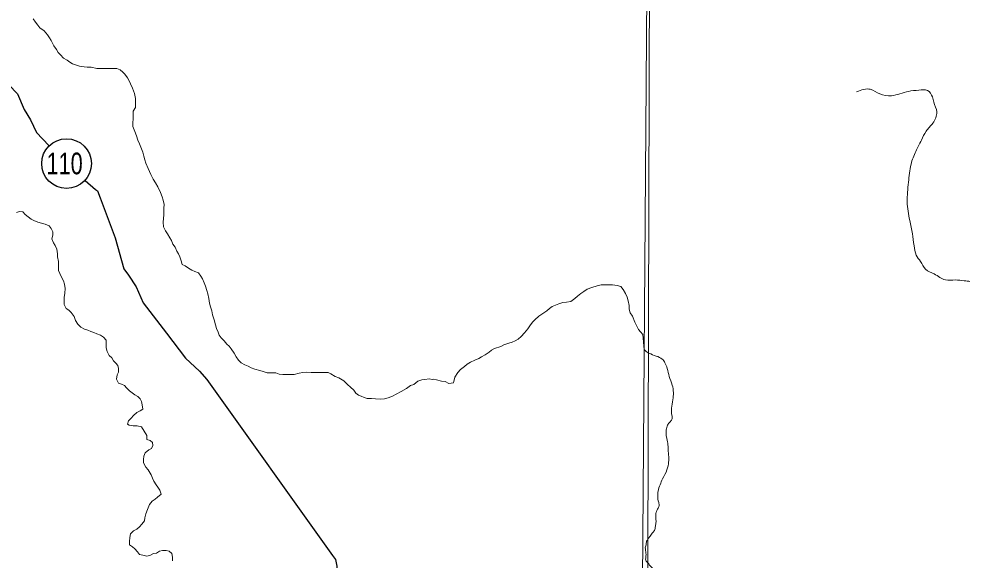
# Model space of a CAD drawing. Extents: x -1643653 to 4543381, y 1624270 to 13878484.
# Drawn here: x 616478 to 619526, y 8901080 to 8902830 of the extents above; entities that cross this region are included whole.
import ezdxf
from ezdxf.enums import TextEntityAlignment as Align

# ---------------------------------------------------------------- set-up
doc = ezdxf.new("R2010")
doc.units = 0
doc.header["$LTSCALE"] = 200
doc.layers.add('1', color=7, linetype='Continuous', lineweight=13)
doc.layers.add('6', color=7, linetype='Continuous', lineweight=13)

msp = doc.modelspace()

# ---------------------------------------------------------------- linework, layer by layer
at = {"layer": '1', "lineweight": 25}
msp.add_spline([(814781, 9009175.5), (814787.2, 9009173.4), (814796.9, 9009173.4), (814799.4, 9009172.4), (814805.1, 9009174.5), (814805.6, 9009176.5), (814811.7, 9009179.5), (814811.7, 9009179.5), (814801.5, 9009181), (814790.7, 9009181.5), (814784.1, 9009183.1), (814777.4, 9009185.1), (814778.4, 9009175.5)], degree=3, dxfattribs=at)
at = {"layer": '6'}
for points in [[(618663, 8924716.1), (618558.3, 8909803.7), (618456.5, 8896026.7)], [(616524, 8902830.2), (616532, 8902818.9), (616539.1, 8902809.7), (616546.1, 8902800.5), (616560.3, 8902791.2), (616570.4, 8902777.9), (616577.4, 8902768.7), (616582.5, 8902759.5), (616591.5, 8902743.1), (616599.6, 8902730.8), (616605.6, 8902721.6), (616612.7, 8902713.4), (616622.8, 8902703.2), (616633.9, 8902696), (616643, 8902689.8), (616651.3, 8902684.9), (616664.3, 8902680.5), (616674.5, 8902677.4), (616688.7, 8902675.3), (616698.9, 8902674.2), (616712.1, 8902674.1), (616730.4, 8902669.9), (616742.6, 8902669.8), (616754.8, 8902669.7), (616772.1, 8902669.6), (616784.3, 8902669.6), (616794.5, 8902669.5), (616805.6, 8902665.3), (616813.7, 8902658.2), (616820.8, 8902651), (616828.8, 8902639.7), (616834.9, 8902629.5), (616838.9, 8902620.3), (616844.9, 8902606), (616851.9, 8902588.6), (616854.8, 8902572.3), (616854.7, 8902555), (616854.6, 8902543.8), (616847.4, 8902531.6), (616847.3, 8902519.4), (616847.2, 8902508.2), (616846.1, 8902492.9), (616846.1, 8902481.7), (616853.1, 8902466.4), (616858.1, 8902452.1), (616863, 8902437.8), (616868, 8902425.5), (616872, 8902415.3), (616879.1, 8902399), (616882, 8902385.7), (616885, 8902374.5), (616888, 8902363.3), (616896, 8902345.9)], [(616896, 8902345.9), (616900, 8902336.7), (616905, 8902326.5), (616912, 8902312.2), (616920.1, 8902299.9), (616927.1, 8902286.6), (616936.1, 8902269.2), (616941.1, 8902254.9), (616944.1, 8902243.7), (616947.1, 8902230.4), (616947, 8902218.2), (616946.9, 8902207), (616946.8, 8902196.8), (616945.7, 8902184.6), (616944.6, 8902172.4), (616945.6, 8902158.1), (616951.6, 8902144.8), (616958.6, 8902134.6), (616965.7, 8902122.3), (616971.7, 8902114.1), (616975.7, 8902101.9), (616982.7, 8902091.7), (616988.8, 8902079.4), (616993.8, 8902070.2), (616997.8, 8902061), (617002.8, 8902047.7), (617005.7, 8902035.5), (617015.9, 8902031.3), (617026, 8902024.1), (617037.2, 8902018), (617046.3, 8902013.8), (617058.5, 8902008.7), (617066.5, 8901998.4), (617071.5, 8901989.2), (617076.5, 8901976.9), (617081.6, 8901965.7), (617085.5, 8901952.4)], [(616470.2, 8902203.8), (616480.3, 8902206.8), (616490.5, 8902205.7), (616498.6, 8902197.5), (616507.7, 8902190.3), (616517.8, 8902182.1), (616526.9, 8902178), (616539.1, 8902172.8), (616551.3, 8902169.7), (616563.5, 8902166.5), (616575.7, 8902161.3), (616582.7, 8902152.1), (616587.7, 8902141.9), (616587.7, 8902130.7), (616584.5, 8902118.5), (616590.5, 8902106.2), (616595.6, 8902097)], [(616595.6, 8902097), (616600.6, 8902085.8), (616602.5, 8902070.5), (616603.4, 8902060.3), (616606.4, 8902046), (616606.3, 8902035.8), (616606.2, 8902016.5), (616610.2, 8902007.3), (616616.2, 8901995), (616622.2, 8901982.8), (616625.2, 8901972.6), (616627.2, 8901958.3), (616627.1, 8901943), (616624.9, 8901928.8), (616624.8, 8901917.6), (616624.8, 8901906.3), (616630.8, 8901894.1), (616639.9, 8901888.9), (616647, 8901880.7), (616657.1, 8901868.4), (616661, 8901855.2), (616669.1, 8901842.9), (616678.2, 8901833.7)], [(617085.5, 8901952.4), (617088.5, 8901941.2), (617092.5, 8901925.9), (617094.4, 8901910.6), (617097.4, 8901899.4), (617101.3, 8901886.1), (617104.3, 8901872.9), (617109.3, 8901857.6), (617113.2, 8901841.2), (617117.2, 8901829), (617122.2, 8901817.7), (617125.2, 8901807.5), (617132.3, 8901799.3), (617141.4, 8901789.1), (617150.5, 8901778.8), (617157.5, 8901771.7), (617164.6, 8901763.5), (617173.7, 8901749.1), (617180.7, 8901737.9), (617187.7, 8901726.6), (617196.8, 8901718.4), (617208, 8901712.2), (617219.1, 8901707.1), (617229.3, 8901701.9), (617240.4, 8901697.8), (617256.7, 8901693.6), (617267.8, 8901690.5), (617281, 8901686.3), (617293.2, 8901686.2), (617308.5, 8901686.1), (617319.7, 8901682), (617330.8, 8901680.9), (617345.1, 8901680.8), (617355.3, 8901680.7), (617367.5, 8901680.7), (617383.8, 8901684.6), (617396, 8901686.6), (617407.2, 8901687.5), (617422.5, 8901687.4), (617437.7, 8901687.3), (617454, 8901687.2), (617464.2, 8901687.2), (617477.4, 8901687.1), (617486.5, 8901682.9), (617500.7, 8901673.7), (617511.8, 8901669.6), (617528.1, 8901660.3), (617540.2, 8901648), (617550.3, 8901639.8), (617560.4, 8901629.5), (617567.5, 8901620.3), (617575.6, 8901614.1), (617584.7, 8901610), (617593.8, 8901605.9), (617604, 8901602.7), (617618.2, 8901602.6), (617630.4, 8901601.6), (617646.7, 8901600.4), (617659.9, 8901601.4), (617671.1, 8901605.4), (617685.4, 8901610.4), (617697.6, 8901616.4), (617713, 8901625.5), (617730.3, 8901635.6), (617743.6, 8901644.6)], [(617882.8, 8901653.4), (617884.2, 8901658.2), (617887.4, 8901671.5), (617896.6, 8901686.7), (617905.8, 8901696.8), (617918.1, 8901705.9), (617927.3, 8901714), (617937.6, 8901720), (617951.8, 8901727.1), (617964.1, 8901732.1), (617973.3, 8901737.1), (617985.5, 8901744.2), (617997.8, 8901752.3), (618006, 8901759.3), (618015.2, 8901764.4), (618035.6, 8901771.4), (618045.8, 8901776.4), (618061.1, 8901781.4), (618072.3, 8901785.4), (618081.5, 8901789.4), (618091.7, 8901794.4), (618100.9, 8901803.6), (618112.2, 8901814.7), (618123.4, 8901827.9), (618129.6, 8901838), (618137.8, 8901849.2), (618145, 8901857.3), (618158.3, 8901869.4), (618171.6, 8901877.5), (618183.8, 8901886.6), (618193.1, 8901893.6), (618201.2, 8901900.7), (618212.5, 8901904.7), (618222.7, 8901908.7), (618235.9, 8901912.7), (618248.1, 8901913.7), (618261.4, 8901916.6), (618274.7, 8901925.7), (618283.9, 8901933.8), (618294.1, 8901941.9), (618304.3, 8901948.9), (618314.5, 8901956), (618329.8, 8901962), (618347.2, 8901967), (618359.4, 8901970), (618382.8, 8901969.8), (618396, 8901969.8), (618411.3, 8901968.6), (618423.4, 8901964.5), (618431.5, 8901955.3), (618438.5, 8901942), (618443.6, 8901930.7), (618447.5, 8901918.5), (618450.5, 8901903.2), (618450.4, 8901892), (618453.4, 8901879.7), (618461.4, 8901868.5), (618468.4, 8901850.1), (618476.5, 8901834.8), (618480.5, 8901825.6), (618487.5, 8901818.4), (618494.6, 8901809.2), (618499, 8901761.6)], [(616678.2, 8901833.7), (616690.3, 8901827.5), (616700.5, 8901823.3), (616710.6, 8901819.2), (616720.8, 8901816.1), (616729.9, 8901811.9), (616742.1, 8901807.8), (616751.2, 8901800.6), (616760.3, 8901791.4), (616760.2, 8901780.2), (616760.1, 8901766.9), (616763.1, 8901754.7), (616770.1, 8901741.4), (616778.2, 8901734.2), (616784.2, 8901725), (616791.3, 8901716.8), (616798.4, 8901709.6), (616800.3, 8901699.4), (616800.3, 8901688.2), (616796.1, 8901679.1), (616794, 8901665.8), (616800, 8901652.6), (616810.2, 8901649.4), (616819.3, 8901645.3), (616826.4, 8901637.1), (616835.5, 8901627.9), (616844.6, 8901621.7), (616852.7, 8901614.5), (616862.8, 8901609.4), (616869.9, 8901602.2), (616874.9, 8901593), (616876.8, 8901582.8), (616878.8, 8901568.5), (616870.6, 8901562.5), (616859.4, 8901557.4), (616848.1, 8901548.3), (616840.9, 8901539.2), (616832.8, 8901531.1), (616829.6, 8901519.9), (616834.3, 8901517)], [(617743.6, 8901644.6), (617754.8, 8901648.6), (617767.1, 8901658.7), (617779.9, 8901663.6), (617790.1, 8901664.4), (617803.5, 8901666), (617813.7, 8901664.4), (617818.3, 8901665.2), (617827.8, 8901663.6), (617844.2, 8901658.9), (617856, 8901657.3), (617867.8, 8901651.8), (617882.8, 8901653.4)], [(616834.3, 8901517), (616847.9, 8901514.7), (616860.7, 8901515), (616874.9, 8901511.8), (616892, 8901483.2), (616891.9, 8901470), (616902.1, 8901466.8), (616910.2, 8901460.7), (616911.1, 8901450.5), (616907, 8901441.3), (616897.8, 8901437.3), (616886.6, 8901427.2), (616881.4, 8901416.1), (616881.3, 8901405.9), (616881.2, 8901394.7), (616888.3, 8901381.4), (616896.3, 8901372.1), (616905.4, 8901355.8), (616909.4, 8901345.6), (616914.4, 8901335.3), (616921.5, 8901324.1), (616927.5, 8901315.9), (616933.5, 8901306.7), (616937.5, 8901293.4), (616926.3, 8901284.3), (616918.1, 8901277.3), (616908.9, 8901271.2), (616900.7, 8901260.1), (616893.4, 8901243.8), (616888.2, 8901229.6), (616885.1, 8901217.4), (616884, 8901207.2), (616875.8, 8901197.1), (616867.6, 8901187.9), (616859.4, 8901180.8), (616848.2, 8901174.8), (616839, 8901165.7), (616836.9, 8901153.5), (616835.8, 8901140.2), (616835.7, 8901130.1), (616844.8, 8901122.9), (616852.9, 8901116.7), (616861, 8901107.5), (616868, 8901098.3), (616879.2, 8901096.2), (616891.4, 8901093), (616903.6, 8901096), (616912.8, 8901102.1), (616923, 8901103), (616932.2, 8901109.1), (616942.4, 8901111), (616953.6, 8901111), (616963.7, 8901109.9), (616972.8, 8901101.7), (616974.8, 8901090.5), (616974.7, 8901078.2)]]:
    msp.add_lwpolyline(points, dxfattribs=at)
msp.add_lwpolyline([(618535.2, 8909853.3), (607574.3, 8909890.7), (607543.3, 8898835.3), (618504.2, 8898795.8)], close=True, dxfattribs=at)
at = {"layer": '6', "lineweight": 25}
for points in [[(616044.3, 8903031.2), (616338.7, 8902741.3), (616398.6, 8902682.1), (616445.2, 8902616.8), (616473.6, 8902587.2), (616494.9, 8902537.3), (616516.1, 8902503.6), (616535.3, 8902462.8), (616575.3, 8902420.1)], [(616692.6, 8902307.3), (616726.2, 8902278.1), (616732.3, 8902274), (616740.4, 8902251.6), (616789.8, 8902122.1), (616817, 8902022.2), (616832.2, 8902001.8)], [(616832.2, 8902001.8), (616857.5, 8901964), (616879.7, 8901912), (616954.8, 8901814.1), (617016.6, 8901733.5), (617062.3, 8901691.6), (617085.6, 8901664.1), (617491.1, 8901095.8), (617501.2, 8901082.6), (617505.2, 8901061.2), (617519.8, 8900868.6), (617561, 8900712.6), (617580, 8900602.6), (617583.9, 8900553.7), (617583.7, 8900508.8), (617579.5, 8900483.4), (617569.1, 8900420.2), (617561.6, 8900327.5), (617544.5, 8899823.2), (617553.6, 8899807.9), (617563.8, 8899799.8), (617571, 8899793.8)]]:
    msp.add_lwpolyline(points, dxfattribs=at)
msp.add_circle((616632.2, 8902362.2), 80.3, dxfattribs=at)
at = {"layer": '6'}
for points in [[(619185.4, 8902594.1), (619229.7, 8902602.4), (619260.2, 8902587.2), (619297.6, 8902581.7), (619353, 8902595.5), (619386.3, 8902599.7), (619414, 8902598.3), (619430.6, 8902577.5), (619434.8, 8902560.9), (619444.5, 8902529), (619432, 8902493), (619409.8, 8902466.7), (619394.6, 8902437.6), (619376.6, 8902401.6), (619361.3, 8902360), (619353, 8902301.8), (619348.9, 8902238.1), (619357.2, 8902178.5), (619365.5, 8902135.6), (619371, 8902096.8), (619378, 8902066.3), (619391.8, 8902045.5), (619408.4, 8902020.6), (619436.2, 8902005.4), (619472.2, 8901986), (619504, 8901986), (619533.1, 8901983.2), (619552.5, 8901980.4), (619581.6, 8901952.7), (619601, 8901927.8), (619628.7, 8901891.8), (619645.3, 8901864.1), (619663.3, 8901839.1), (619663.3, 8901812.8), (619663.8, 8901792.9), (619665.6, 8901776.9), (619669.4, 8901761.8), (619673.2, 8901744.9), (619684, 8901732.2), (619697.6, 8901723.7), (619722.6, 8901713.8), (619749.9, 8901713.4), (619772.4, 8901712.4), (619785.6, 8901712.4), (619810.1, 8901719), (619828.4, 8901722.8), (619849.6, 8901727.5), (619870.3, 8901732.2), (619891.9, 8901732.7), (619914.5, 8901727.5), (619939.5, 8901714.3), (619956.4, 8901704), (619975.7, 8901693.2), (619996.4, 8901679), (620013.8, 8901663.5)], [(618499, 8901761.6), (618503.2, 8901756.5), (618514.3, 8901749.3), (618537.3, 8901740.1), (618557.5, 8901729.9), (618566, 8901718.5), (618573.2, 8901700), (618580, 8901674.2), (618589.5, 8901646.4), (618593.3, 8901621.8), (618591.2, 8901598.9), (618587.7, 8901571.1), (618588.4, 8901548.8), (618589.1, 8901537), (618583.5, 8901528.6), (618575.9, 8901520.3), (618571, 8901505), (618569.5, 8901492.9), (618571.1, 8901478.9), (618575.3, 8901458.1), (618576.3, 8901438.2), (618578.3, 8901414.3), (618577.9, 8901397.7), (618572.6, 8901372.7), (618558.5, 8901343), (618550.3, 8901324.2), (618544.1, 8901303.3), (618542.6, 8901289.4), (618545.9, 8901266.5), (618547.2, 8901256.2), (618542, 8901245.6), (618537.3, 8901235.3), (618536.4, 8901218.2), (618537.1, 8901203.9), (618535, 8901190.1), (618531.9, 8901176.4), (618524.9, 8901167.3), (618516, 8901155.2), (618510.6, 8901147.1), (618506.1, 8901139.1), (618505.3, 8901129.8), (618503, 8901122.9), (618503.4, 8901111.4), (618504.7, 8901093.6), (618504.2, 8901080), (618511.5, 8901070.3), (618519.3, 8901061), (618531.9, 8901048.2), (618539.3, 8901039.7), (618544.9, 8901022.6), (618545.9, 8901009.7), (618545.5, 8901001.1), (618542, 8900989.9), (618540.8, 8900979.8), (618540.4, 8900969.7)]]:
    msp.add_spline(points, degree=3, dxfattribs=at)

# ---------------------------------------------------------------- texts
at = {"layer": '6', "width": 0.75}
msp.add_text('110', height=70, dxfattribs=at).set_placement((616625.8, 8902327.6), align=Align.CENTER)

doc.saveas('drawing.dxf')
